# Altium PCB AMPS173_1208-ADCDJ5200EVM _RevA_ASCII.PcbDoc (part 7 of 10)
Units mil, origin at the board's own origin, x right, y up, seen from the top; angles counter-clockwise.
Board outline 10500 x 2750 mil, 14 copper layers (Top Copper, Layer 2 (GND1), Layer 3 (SIG1), Layer 4 (GND2, Layer 5 (PWR1), Layer 6 (GND3), Layer 7 (PWR/SIGNAL2), Layer 8 (PWR/SIGNAL3), Layer 9 (GND4), Layer 10 PWR2), Layer 11 (GND5), Layer 12 (SIG4), Layer 13 (GND6), Bottom Copper), stack 60.6 mil thick; 701 components, 826 nets, 3386 pads, 2128 vias.
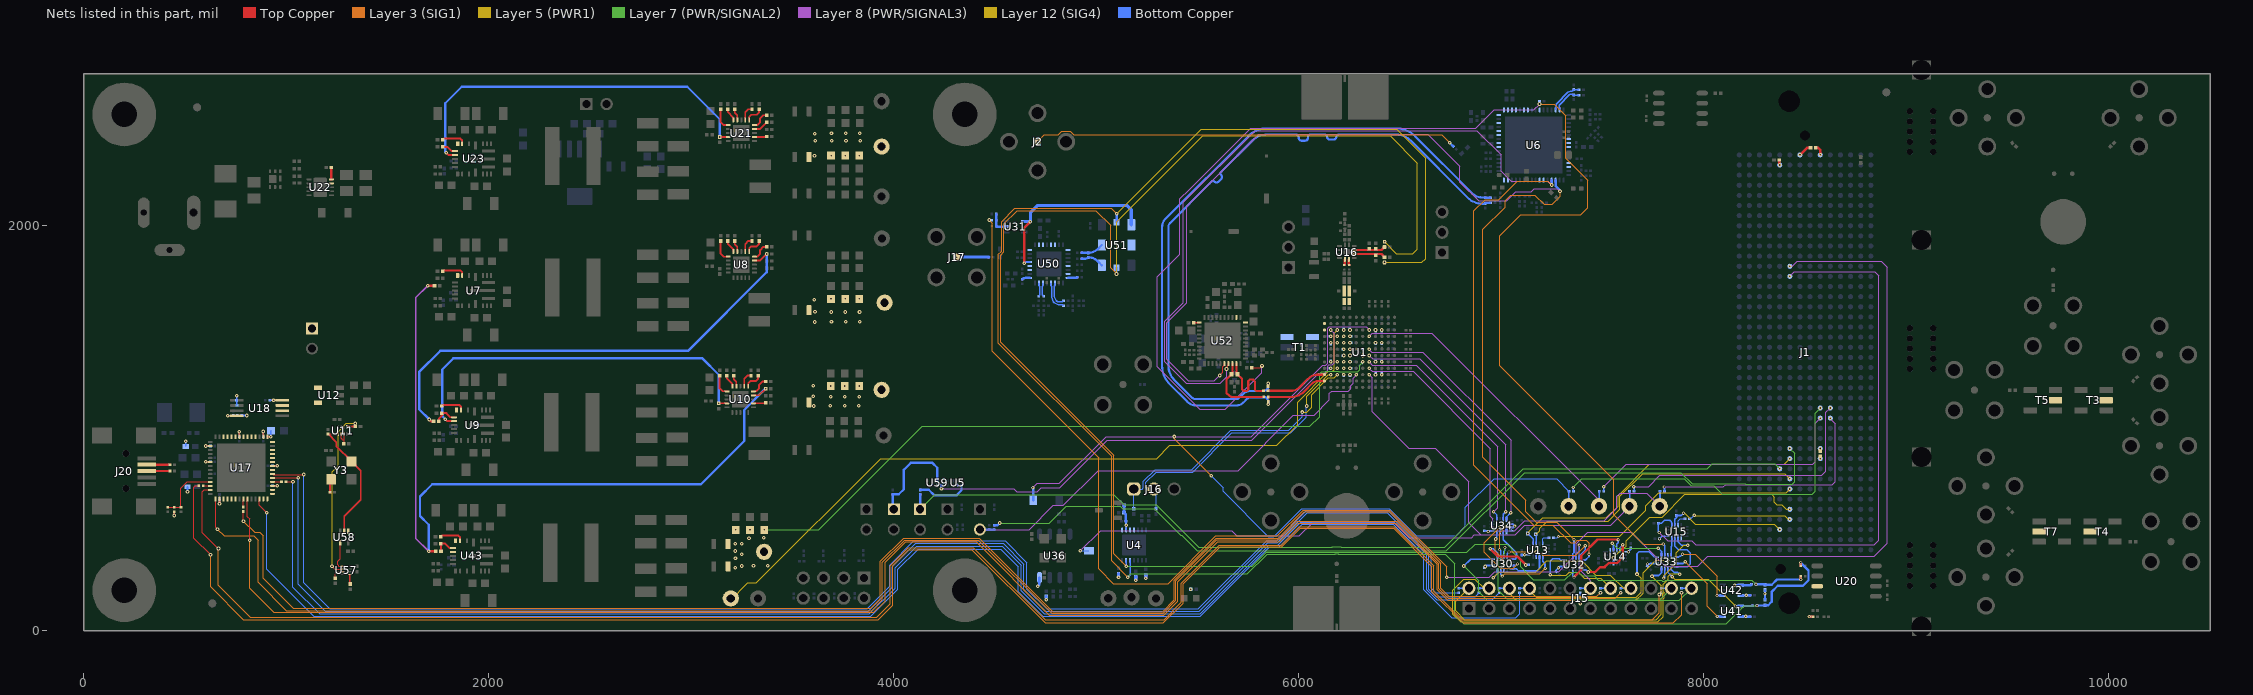
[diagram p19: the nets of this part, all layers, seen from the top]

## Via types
v1: diameter 18, hole 8, Top Copper to Bottom Copper, tented both sides, 1234 vias
v2: diameter 18, hole 8, Top Copper to Bottom Copper, tented top, 219 vias
v3: diameter 16, hole 8, Top Copper to Bottom Copper, tented both sides, 138 vias
v4: diameter 19.68, hole 7.87, Top Copper to Bottom Copper, 103 vias
v5: diameter 20, hole 10, Top Copper to Bottom Copper, tented top, 96 vias
v6: diameter 20, hole 10, Top Copper to Bottom Copper, tented both sides, 71 vias
v7: diameter 15.75/18/18/18/16/18/18/18/18/16/18/18/18/18 (per signal layer), hole 8, Top Copper to Bottom Copper, 50 vias
v8: diameter 20, hole 10, Top Copper to Bottom Copper, 40 vias
v9: diameter 15.75, hole 7.87, Top Copper to Bottom Copper, 28 vias
v10: diameter 21.81, hole 10, Top Copper to Bottom Copper, 26 vias
v11: diameter 15.75/16/16/16/16/16/16/16/16/16/16/16/16/18 (per signal layer), hole 8, Top Copper to Bottom Copper, 26 vias
v12: diameter 18, hole 8, Top Copper to Bottom Copper, tented bottom, 18 vias
v13: diameter 25.75, hole 15.75, Top Copper to Bottom Copper, 16 vias
v14: diameter 15.75/16/16/16/16/16/16/18/16/16/16/16/16/18 (per signal layer), hole 8, Top Copper to Bottom Copper, 15 vias
v15: diameter 30, hole 15, Top Copper to Bottom Copper, tented both sides, 12 vias
v16: diameter 15.75/16/16/16/18/16/16/16/16/16/16/16/16/18 (per signal layer), hole 8, Top Copper to Bottom Copper, 11 vias
v17: diameter 15.75/16/16/16/16/16/16/16/16/18/16/16/16/18 (per signal layer), hole 8, Top Copper to Bottom Copper, 7 vias
v18: diameter 15.75/16/16/16/16/16/16/18/16/18/16/16/16/18 (per signal layer), hole 8, Top Copper to Bottom Copper, 5 vias
v19: diameter 119.29, hole 77.95, Top Copper to Bottom Copper, 4 vias
v20: diameter 18, hole 8, Top Copper to Bottom Copper, 4 vias
v21: diameter 15.75/16/16/16/18/16/16/18/16/16/16/16/16/18 (per signal layer), hole 8, Top Copper to Bottom Copper, 2 vias
v22: diameter 15.75/16/16/16/16/16/18/16/16/16/16/16/16/18 (per signal layer), hole 8, Top Copper to Bottom Copper, 2 vias
v23: diameter 15.75/16/16/16/16/16/18/18/16/16/16/16/16/18 (per signal layer), hole 8, Top Copper to Bottom Copper, 1 vias

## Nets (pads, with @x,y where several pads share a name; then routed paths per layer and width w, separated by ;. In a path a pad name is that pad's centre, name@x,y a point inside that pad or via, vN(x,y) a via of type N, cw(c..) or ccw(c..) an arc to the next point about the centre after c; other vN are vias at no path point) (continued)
NetR99_1: R99.1 U7.16 | length 118
  Top Copper w9.8: R99.1@1772.99,1775 1777.99,1780 1860,1780 1868.9,1771.1 U7.16@1868.9,1754.8
NetR100_2: R100.2 U8.11 | length 106.1
  Top Copper w9: R100.2@3145,1925 3145,1862 3159.63,1847.37 U8.11@3182.04,1847.37
NetR101_2: R101.2 U8.10 | length 63.5
  Top Copper w9: R101.2@3180,1925 3180,1912 3207.63,1884.37 U8.10@3207.63,1872.96
NetR102_2: R102.2 U8.9 | length 57.1
  Top Copper w9: R102.2@3215,1925 3215,1908 3227.32,1895.69 U8.9@3227.32,1872.96
NetR110_2: R110.2 U8.7 | length 76.4
  Top Copper w9: U8.7@3266.69,1872.96 3266.69,1909.69 3282,1925 R110.2@3300,1925
NetR111_2: R111.2 U8.6 | length 87.7
  Top Copper w9: U8.6@3286.37,1872.96 3286.37,1888.37 3296,1898 3322.54,1898 3335,1910.46 R111.2@3335,1925
NetR112_2: R112.2 U8.5 | length 90.6
  Top Copper w9: U8.5@3311.96,1847.37 3325.37,1847.37 3340,1862 3340,1880 3355.75,1895.75 R112.2@3372.01,1895.75
NetR116_2: R116.2 U9.19 U10.14 | length 1903.9
  Top Copper w9: R116.2@3135,1122.99 v1(3135.32,1123.31) U10.14@3177.04,1123.31
  Top Copper w9.8: v1(1785,1045) 1795.32,1034.68 U9.19@1828.46,1034.68
  Bottom Copper w11.5: v1(1785,1045) 1770,1060 1770,1290 1825,1345 3055,1345 3135.32,1264.68 v1(3135.32,1123.31)
NetR117_1: R117.1 R280.1 U9.18 | length 115.5
  Top Copper w9.8: R280.1@1752.99,1035 1752.99,1047.99 1767.5,1062.5 1767.99,1062.5 R117.1@1767.99,1075 1790,1075 1810.63,1054.37 U9.18@1828.46,1054.37
NetR118_1: R118.1 U10.2 | length 61.1
  Top Copper w9: U10.2@3306.96,1123.31 3364.57,1123.31 R118.1@3367.01,1125.75
NetR119_1: R119.1 U9.16 | length 118
  Top Copper w9.8: R119.1@1767.99,1110 1772.99,1115 1855,1115 1863.9,1106.1 U9.16@1863.9,1089.8
NetR120_2: R120.2 U10.11 | length 106.1
  Top Copper w9: R120.2@3140,1260 3140,1197 3154.63,1182.37 U10.11@3177.04,1182.37
NetR122_2: R122.2 U10.10 | length 63.5
  Top Copper w9: R122.2@3175,1260 3175,1247 3202.63,1219.37 U10.10@3202.63,1207.96
NetR123_2: R123.2 U10.9 | length 57.1
  Top Copper w9: R123.2@3210,1260 3210,1243 3222.32,1230.68 U10.9@3222.32,1207.96
NetR124_2: R124.2 U10.7 | length 76.4
  Top Copper w9: U10.7@3261.69,1207.96 3261.69,1244.69 3277,1260 R124.2@3295,1260
NetR125_2: R125.2 U10.6 | length 87.7
  Top Copper w9: U10.6@3281.37,1207.96 3281.37,1223.37 3291,1233 3317.54,1233 3330,1245.46 R125.2@3330,1260
NetR126_2: R126.2 U10.5 | length 90.6
  Top Copper w9: U10.5@3306.96,1182.37 3320.37,1182.37 3335,1197 3335,1215 3350.75,1230.75 R126.2@3367.01,1230.75
NetR127_1: R127.1 U11.5 U57.2 | length 892.2
  Top Copper w6: v1(1226,318) 1239.11,304.89 U57.2@1278.28,304.89
  Top Copper w9: U11.5@1299.92,1006.58 1302.2,1008.87 R127.1@1340.13,1008.87 v1(1340.13,1023.75)
  Layer 12 (SIG4) w6: v1(1226,318) 1226,786 1256,816 1256,983 1296.75,1023.75 v1(1340.13,1023.75)
NetR128_1: R128.1 U11.2 U11.3 | length 86.5
  Top Copper w6: U11.2@1271.24,971.15 1271.24,949.76 1277,944 1285,944 ; R128.1@1283.01,923 1285,924.99 1285,944 ; U11.3@1285.02,971.15 1285.02,944.02
NetR129_1: R129.1 U57.3 | length 63.1
  Top Copper w4: R129.1@1241,259.99 1241,282 1250.11,291.11 U57.3@1278.28,291.11
NetR132_1: R132.1 U21.14 U23.19 | length 1879.6
  Top Copper w9: R132.1@3140,2437.99 v1(3140.32,2438.31) U21.14@3182.04,2438.31
  Top Copper w9.8: v1(1790,2360) 1800.32,2349.68 U23.19@1833.46,2349.68
  Bottom Copper w11.5: v1(1790,2360) 1785,2365 1785,2605 1866,2686 2980,2686 3140.32,2525.68 v1(3140.32,2438.31)
NetR134_1: R134.1 U23.18 | length 69
  Top Copper w9.8: R134.1@1772.99,2390 1795,2390 1815.63,2369.37 U23.18@1833.46,2369.37
NetR135_1: R135.1 U21.2 | length 61.1
  Top Copper w9: U21.2@3311.96,2438.31 3369.57,2438.31 R135.1@3372.01,2440.75
NetR136_1: R136.1 U23.16 | length 118
  Top Copper w9.8: R136.1@1772.99,2425 1777.99,2430 1860,2430 1868.9,2421.1 U23.16@1868.9,2404.8
NetR137_2: R137.2 U21.11 | length 106.1
  Top Copper w9: R137.2@3145,2575 3145,2512 3159.63,2497.37 U21.11@3182.04,2497.37
NetR139_2: R139.2 U21.10 | length 63.5
  Top Copper w9: R139.2@3180,2575 3180,2562 3207.63,2534.37 U21.10@3207.63,2522.96
NetR140_2: R140.2 U21.9 | length 57.1
  Top Copper w9: R140.2@3215,2575 3215,2558 3227.32,2545.68 U21.9@3227.32,2522.96
NetR141_2: R141.2 U21.7 | length 76.4
  Top Copper w9: U21.7@3266.69,2522.96 3266.69,2559.69 3282,2575 R141.2@3300,2575
NetR142_2: R142.2 U21.6 | length 87.7
  Top Copper w9: U21.6@3286.37,2522.96 3286.37,2538.37 3296,2548 3322.54,2548 3335,2560.46 R142.2@3335,2575
NetR143_2: R143.2 U21.5 | length 90.6
  Top Copper w9: U21.5@3311.96,2497.37 3325.37,2497.37 3340,2512 3340,2530 3355.75,2545.75 R143.2@3372.01,2545.75
NetR145_2: R145.2 U22.10 | length 58.5
  Top Copper w11.5: U22.10@1222.55,2229.5 R145.2@1222.55,2288
NetR153_1: R153.1 U17.12 | length 34.8
  Top Copper w5: R153.1@590.02,716 624.74,716 U17.12@624.82,715.92
NetR155_1: R155.1 U17.22 | length 39.6
  Top Copper w6: U17.22@788.2,650.96 788.5,650.66 R155.1@788.5,611.52
NetR160_2: R160.2 U17.6 | length 43.8
  Top Copper w5: v1(603.03,834.03) U17.6@624.82,834.03
  Bottom Copper w5: v1@603.06,834 R160.2@624.98,834
NetR162_2: R162.2 R165.2 R166.1 U17.11 | length 317.9
  Top Copper w5: R162.2@414,610.02 R165.2@447,610 R166.1@480,610.02 480,704 511.6,735.6 U17.11@624.82,735.6
NetR163_1: R163.1 U17.32 | length 44.1
  Top Copper w5: U17.32@931.91,735.6 975.87,735.6 R163.1@975.98,735.5
NetR169_1: R169.1 R170.1 U18.4 | length 93.9
  Top Copper w5: v1(710.59,1061.41) U18.4@756,1061.41
  Bottom Copper w5: v1(710.59,1061.41) 713.16,1063.98 R170.1@737,1063.98 R169.1@757.98,1064
NetR175_2: R175.2 U11.1 U58.2 Y3.3 | length 632.7
  Top Copper w5: R175.2@1208.76,973.12 U11.1@1257.46,973.12
  Top Copper w7: R175.2@1208.76,973.12 ccw(c1208.76,969.22) R175.2@1206,971.98 1247,930.98 1247,911.28 Y3.3@1322.13,836.16 1368,790.28 1368,648 1286,566 U58.2@1286,492.13
NetR178_1: R178.1 U13.4 | length 58.5
  Bottom Copper w6: U13.4@7204.37,429.84 7204.37,454.37 7210,460 R178.1@7235.98,460
NetR180_1: R180.1 U16.12 | length 26.5
  Top Copper w11.5: U16.12@6246.92,1833.67 6246.92,1809.99 R180.1@6248.92,1807.99
NetR181_2: R181.2 R182.1 R184.2
NetR182_2: R182.2 R183.1
NetR185_1: R185.1 U16.11 | length 26.6
  Top Copper w11.5: R185.1@6224.92,1807.99 6227.23,1810.31 U16.11@6227.23,1833.67
NetR186_2: R186.2 R187.1 R189.2
NetR187_2: R187.2 R188.1
NetR207_1: R207.1 U15.3 | length 61.1
  Bottom Copper w6: U15.3@7872.87,521.5 7872.87,542.87 7884,554 R207.1@7907.98,554
NetR226_1: R226.1 R238.2 U6.62 | length 169.7
  Bottom Copper w7: U6.62@7268.58,2572.05 7268.58,2583.34 cw(c7278.29,2583.34) 7269.26,2586.9 ccw(c7264.02,2592.13) 7271.05,2589.81 ccw(c7264.02,2592.13) 7271.43,2592.13 7271.43,2596 cw(c7285.43,2596) 7275.52,2605.89 ; 7275.53,2605.9 7326.29,2656.66 cw(c7344,2638.96) 7344,2664 ccw(c7344,2676.64) 7352.94,2667.7 R238.2@7358.19,2672.95 ccw(c7360.55,2675.31) 7360.55,2671.98 R226.1@7383.17,2671.98
NetR227_1: R227.1 R256.2 U6.63 | length 145.7
  Bottom Copper w7: U6.63@7288.27,2572.05 7288.27,2583.34 cw(c7295.13,2590.21) 7285.43,2590.21 7285.43,2596 7336.19,2646.77 cw(c7344,2638.96) 7344,2650 7346.12,2650 cw(c7346.12,2632.93) R256.2@7358.19,2645 R227.1@7383.17,2644.98
NetR230_1: R230.1 R888.1 U43.18 | length 106.9
  Top Copper w9.8: R888.1@1763.78,392.43 1762.99,393.22 R230.1@1762.99,430 1785,430 1805.63,409.37 U43.18@1823.46,409.37
NetR231_1: R231.1 U43.16 | length 118
  Top Copper w9.8: R231.1@1762.99,465 1767.99,470 1850,470 1858.9,461.1 U43.16@1858.9,444.8
NetR233_1: R233.1 U57.5 | length 47.3
  Top Copper w7: R233.1@1313.72,233.28 U57.5@1313.72,277.33
  Top Copper w11.5: R233.1@1313.72,233.28 R233.1@1316,230.99
NetR239_1: R239.1 U50.9 | length 38.6
  Bottom Copper w11.5: R239.1@4635,1736.02 cw(c4651.06,1719.96) 4651.06,1742.68 U50.9@4671.81,1742.68
NetR240_1: R240.1 U50.3 | length 129.1
  Bottom Copper w7: U50.3@4795.83,1717.09 4795.83,1705.8 ccw(c4802.69,1698.93) 4792.98,1698.93 4792.98,1653.92 ccw(c4826.91,1653.92) 4802.92,1629.93 ccw(c4816.51,1643.52) 4816.51,1624.3 4829.14,1624.3 ccw(c4829.14,1631.81) 4834.45,1626.5 R240.1@4837.95,1630
NetR241_1: R241.1 U50.32 | length 46.4
  Bottom Copper w11.5: U50.32@4860.79,1742.68 4903.46,1742.68 R241.1@4906.06,1745.28
NetR242_1: R242.1 U50.4 | length 151
  Bottom Copper w7: U50.4@4776.14,1717.09 4776.14,1705.8 cw(c4769.28,1698.93) 4778.98,1698.93 4778.98,1653.92 ccw(c4826.91,1653.92) 4793.02,1620.03 ccw(c4816.51,1643.52) 4816.51,1610.3 4830.11,1610.3 cw(c4830.11,1604.15) 4834.45,1608.5 R242.1@4837.95,1605
NetR246_1: R246.1 U50.6 | length 67.9
  Bottom Copper w7: U50.6@4736.77,1717.09 4736.77,1705.8 ccw(c4743.63,1698.93) 4733.93,1698.93 4733.93,1661.75 ccw(c4742.71,1661.75) 4736.5,1655.55 R246.1@4740,1652.05
NetR247_1: R247.1 U50.7 | length 67.6
  Bottom Copper w7: R247.1@4715,1652.05 4718.5,1655.55 ccw(c4715.05,1659) 4719.93,1659 4719.93,1698.93 ccw(c4710.22,1698.93) 4717.09,1705.8 U50.7@4717.09,1717.09
NetR254_1: R254.1 U5.4 | length 249.8
  Bottom Copper w11.5: R254.1@4130,696.02 4172.98,696.02 4199,670 4311,670 4334.69,693.68 U5.4@4334.69,718.19
NetR262_1: R262.1 U52.1 | length 27.7
  Top Copper w8: R262.1@5481.2,1521.79 5481.36,1521.96 U52.1@5508.86,1521.96
NetR277_1: R277.1 R278.1 R279.2 U31.2 | length 111
  Bottom Copper w11.5: R279.2@4506.02,2058.19 R278.1@4506.02,2028.19 R277.1@4506.02,1998.19 4509.21,1995 U31.2@4555.71,1995
NetR305_1: R305.1 U30.1 | length 291.4
  Top Copper w11.5: v1(6945,405) 6983.58,366.42 7079.96,366.42 v1(7121.38,325)
  Bottom Copper w7: v1(6945,405) 6960,405 6981.38,383.62 U30.1@6981.38,359.53
  Bottom Copper w11.5: v1(7121.38,325) R305.1@7133.98,325
NetR801_2: R801.2 Y3.1 | length 65.7
  Top Copper w11.5: R801.2@1215.87,684.44 1215.87,741.32 Y3.1@1222.13,747.57
NetR804_1: R804.1 U42.4 | length 84.8
  Bottom Copper w11.5: v3(8153,225) U42.4@8182.29,225 8231.54,225 R804.1@8235.95,229.41
NetR852_1: R852.1 U33.10 U41.4 | length 508
  Layer 12 (SIG4) w3.3: v3(7844,267) 7856,255 8023,255 v3(8155.68,122.32)
  Bottom Copper w8: U33.10@7822.87,308.5 7822.87,288.13 v3(7844,267)
  Bottom Copper w11.5: v3(8155.68,122.32) U41.4@8182.29,122.32 8238.87,122.32 R852.1@8240.95,124.41
NetT1_1: T1.1
NetT1_6: T1.6
NetT3_2: T3.2
NetT4_2: T4.2
NetT5_2: T5.2
NetT7_2: T7.2
NetU1_B1: U1.B1
NetU1_C1: U1.C1
NetU4_1: U4.1
NetU4_3: U4.3
NetU4_4: U4.4
NetU5_5: U5.5
NetU6_7: U6.7
NetU6_8: U6.8
NetU6_9: U6.9
NetU6_13: U6.13
NetU6_14: U6.14
NetU6_22: U6.22
NetU6_23: U6.23
NetU6_31: U6.31
NetU6_32: U6.32
NetU6_40: U6.40
NetU6_41: U6.41
NetU6_43: U6.43
NetU6_44: U6.44
NetU6_46: U6.46
NetU6_48: U6.48
NetU6_49: U6.49
NetU6_50: U6.50
NetU6_51: U6.51
NetU6_52: U6.52
NetU6_54: U6.54
NetU6_55: U6.55
NetU6_58: U6.58
NetU7_17: U7.17
NetU9_17: U9.17
NetU12_4: U12.4
NetU12_5: U12.5
NetU13_9: U13.9 U30.11 | length 323.6
  Layer 3 (SIG1) w3.3: v3(7005,270) 7016,281 7190,281 v3(7217,308)
  Bottom Copper w8: U30.11@6997.13,298.5 6997.13,277.87 v3(7005,270) ; U13.9@7204.37,366.85 7204.37,342.63 7216,331 7216,309 v3(7217,308)
NetU13_10: U13.10 U30.8 | length 205
  Bottom Copper w8: U30.8@7052.24,306.38 7073.62,306.38 7085,295 7175,295 7188.68,308.68 7188.68,366.79 U13.10@7188.62,366.85
NetU13_11: U13.11 U30.4 U32.4 | length 536
  Layer 3 (SIG1) w3.3: v3(7038,389) 7038.65,389.65 7172.4,389.65 v3(7172.87,390.13) 7185.87,390.13 7204,372 7367,372 v3(7415,420)
  Bottom Copper w8: U30.4@7028.62,361.5 7028.62,379.62 v3(7038,389) ; U13.11@7172.87,366.85 v3(7172.87,390.13) ; U32.4@7383.62,356.5 7383.62,367.62 7415,399 v3(7415,420)
NetU14_9: U14.9
NetU14_10: U14.10 U33.1 | length 319.8
  Layer 7 (PWR/SIGNAL2) w3.3: v3(7548,432) 7572,408 v3(7775,408) v3@7776.01,408
  Bottom Copper w8: v3(7548,432) 7554.25,425.75 U14.10@7554.25,397.99 ; v3(7775,408) 7791.38,391.62 U33.1@7791.38,369.53
NetU14_11: U14.11 U32.11 | length 421.3
  Top Copper w11.5: v3(7359,265) 7395,301 7395,370 7475.75,450.75 7575.25,450.75 v3(7577,449)
  Bottom Copper w8: U32.11@7352.13,293.5 7352.13,271.87 v3(7359,265) ; U14.11@7570,397.99 7570,428 7577,435 v3(7577,449)
NetU14_12: U14.12 U32.8 | length 322
  Top Copper w11.5: v1(7430,290) 7464.14,290 7488.39,314.25 7510.25,314.25 7531,335 7571,335 7600,364 v1(7600,425)
  Bottom Copper w8: U32.8@7407.24,301.38 7418.62,301.38 v1(7430,290) ; U14.12@7585.75,397.99 7585.75,410.75 v1(7600,425)
NetU15_9: U15.9
NetU15_10: U15.10 U33.11 | length 349.4
  Layer 12 (SIG4) w3.3: v3@7803.01,260 7803.01,272 7864.01,333 7864.01,386 7900.01,422 v3(7921,422) v3@7922.01,422
  Bottom Copper w8: v3(7802,260) 7807.13,265.13 U33.11@7807.13,308.5 ; U15.10@7872.87,458.5 7872.87,439.13 7890,422 v3(7921,422)
NetU15_11: U15.11 U33.8 | length 261.6
  Bottom Copper w8: U15.11@7857.13,458.5 7857.13,418.13 7875.25,400 7917,400 7934,383 7934,331 7919.38,316.38 U33.8@7862.24,316.38
NetU15_12: U15.12 U33.4 | length 88.1
  Bottom Copper w8: U33.4@7838.62,371.5 7838.62,416.24 7841.38,419 U15.12@7841.38,458.5
NetU17_17: U17.17
NetU17_18: U17.18
NetU17_19: U17.19
NetU17_20: U17.20
NetU17_27: U17.27
NetU17_28: U17.28
NetU17_29: U17.29
NetU17_30: U17.30
NetU17_35: U17.35
NetU17_37: U17.37
NetU17_38: U17.38
NetU17_39: U17.39
NetU17_40: U17.40
NetU17_42: U17.42
NetU17_46: U17.46
NetU17_47: U17.47
NetU17_48: U17.48
NetU17_49: U17.49
NetU17_51: U17.51
NetU17_52: U17.52
NetU17_53: U17.53
NetU17_54: U17.54
NetU18_6: U18.6
NetU18_7: U18.7
NetU20_7: U20.7
NetU22_9: U22.9
NetU23_17: U23.17
NetU30_2: U30.2 U34.1 | length 196.9
  Layer 3 (SIG1) w3.3: v3@6992.01,401 6992.01,484 v3@7023.01,515
  Bottom Copper w8: v3(6991,401) 6997.13,394.87 U30.2@6997.13,361.5 ; v3(7022,515) 7025.62,511.38 U34.1@7025.62,488.47
NetU30_5: U30.5 U34.2 | length 178.9
  Bottom Copper w8: U34.2@7009.87,486.5 7009.94,486.44 7009.94,450.06 7075,385 7075,360 7068.62,353.62 U30.5@7052.24,353.62
NetU30_7: U30.7 U34.3 | length 425.3
  Layer 3 (SIG1) w3.3: v3@6995.13,513.87 6916,434.74 6916,387.66 6994.69,308.97 7059.98,308.97 v3@7081.01,330
  Bottom Copper w8: v3@6993,515 v3(6994.13,513.87) U34.3@6994.13,486.5 ; U30.7@7052.24,322.13 7072.13,322.13 v3(7080,330)
NetU30_10: U30.10 U34.4 | length 208.4
  Layer 3 (SIG1) w3.3: v1(6972,453) 6971.01,452.01 6971.01,392.19 7010,353.2 v3(7010,325)
  Bottom Copper w8: v1(6972,453) 6978.38,459.38 U34.4@6978.38,486.5 ; v3(7010,325) 7012.87,322.13 U30.10@7012.87,298.5
NetU31_4: U31.4 U50.13 U51.1 | length 917.9
  Top Copper w11.5: v1(4645,1815) 4645,1991.18 v1(4674.41,2020.59)
  Bottom Copper w11.5: v1(4645,1815) 4651.42,1821.42 U50.13@4671.81,1821.42
  Bottom Copper w15.5: U31.4@4644.29,2020.59 v1(4674.41,2020.59) 4674.41,2064.94 4710.25,2100.78 5150.92,2100.78 5172.83,2078.87 U51.1@5172.83,2005
NetU33_5: U33.5 U42.1 | length 378.5
  Layer 3 (SIG1) w3.3: v3@7896.01,378 7958.01,378 8066.19,269.82 v3@8066.19,173.82
  Bottom Copper w8: U33.5@7862.24,363.62 7875.58,363.62 7879.96,368 7885,368 v3(7895,378)
  Bottom Copper w11.5: v3@8065,174 v3(8065.18,173.82) U42.1@8093.71,173.82
NetU33_7: U33.7 U41.1 | length 412.6
  Layer 3 (SIG1) w3.3: v3@7909.01,341 8017.4,232.61 8017.4,120.61 v3@8067.01,71
  Bottom Copper w8: U33.7@7862.24,332.13 7899.13,332.13 v3(7908,341)
  Bottom Copper w11.5: v3(8066,71) 8066.14,71.14 U41.1@8093.71,71.14
NetU43_17: U43.17
NetU43_19: U43.19
NetU50_11: U50.11
NetU50_12: U50.12
NetU50_16: U50.16
NetU50_18: U50.18
NetU50_19: U50.19
NetU50_21: U50.21
NetU50_22: U50.22
NetU50_25: U50.25
NetU50_29: U50.29
NetU50_31: U50.31
NetU51_2: U51.2
NetU52_30: U52.30
NetU52_32: U52.32
NetU57_1: U57.1 U58.4 | length 144.3
  Top Copper w6: U58.4@1266.32,433.87 1266.32,356.32 1253,343 1253,325 1259.33,318.67 U57.1@1280.25,318.67
NetU58_1: U58.1
NetU59_5: U59.5
ORA0_ADC: D4.2 R33.2 TP8.1 U1.C8 | length 4717
  Layer 3 (SIG1) w5: v1(5385,959) 5385,948 v1(5567,766)
  Layer 8 (PWR/SIGNAL3) w3.3: v3(4687,706) 4709,728 4818,728 5049,959 v1(5385,959) 5766,959 6118.91,1311.91 6133.06,1311.91 6142.62,1321.47 6142.62,1493.62 6150,1501 6332.49,1501 6348.25,1485.24 v14(6347.24,1485.24)
  Bottom Copper w5: v1(5567,766) 5626,707 5626,688.95 5849.95,465 5876,465 6014,603 6447,603 6581,469 6777,469 6823,515 6823,608.95 6965,750.95 7273.02,750.95 R33.2@7333.98,690
  Bottom Copper w8: TP8.1@7332.5,615 7333.98,616.48 R33.2@7333.98,690
  Bottom Copper w11.5: v3(4687,706) 4688.52,704.48 D4.2@4688.52,644.57
ORA0_FMC: J1.D26 R33.1 | length 1692.8
  Layer 7 (PWR/SIGNAL2) w4: v3(7355,708) 7397.95,750.95 7904.27,750.95 7939.27,715.95 8048,715.95 8090,673.95 8536,673.95 8550,687.95 8550,1075 v1(8575,1100)
  Layer 7 (PWR/SIGNAL2) w8: v3(7355,708) v3@7356.02,706.98
  Bottom Copper w8: v3(7355,708) 7356.02,706.98 R33.1@7356.02,690
ORA1_ADC: R36.2 TP12.1 U1.D8 | length 1588.4
  Layer 8 (PWR/SIGNAL3) w3.3: v14@6348.25,1453.74 6348.25,1454.24 6363.59,1469.59 6657.41,1469.59 7483,644 7483,615.5 TP12.1@7483.51,615
  Bottom Copper w8: TP12.1@7482.5,615 7483.98,616.48 R36.2@7483.98,690
  other v14: 6347.24,1453.74
ORA1_FMC: J1.D27 R36.1 | length 1342.9
  Layer 8 (PWR/SIGNAL3) w4: v3(7506,711) 7616.95,821.95 8539,821.95 8551,833.95 8551,1026 v1(8575,1050)
  Bottom Copper w8: R36.1@7506.02,690 v3(7506,711)
ORB0_ADC: D5.2 R71.2 TP13.1 U1.K8 | length 4098.6
  Layer 8 (PWR/SIGNAL3) w3.3: v1(4921.47,394.47) 5021,494 5669,494 5694,469 6003,469 6068,534 6472,534 6546,460 6853,460 6867.35,474.35 6898.65,474.35 ; v14@6348.25,1264.76 6363,1250.02 6363,1081.69 6543,901.69 6673.85,901.69 6839.31,736.23 6839.31,533.69 6898.65,474.35 ; TP13.1@7633.51,615 7540.64,522.13 7116.23,522.13 7068.46,474.35 6898.65,474.35
  Bottom Copper w4: v1(4921.47,394.47) D5.2@4964,394.47
  Bottom Copper w8: TP13.1@7632.5,615 7633.98,616.48 R71.2@7633.98,690
  other v14: 6347.24,1264.76
ORB0_FMC: J1.C26 R71.1 | length 1324.5
  Layer 8 (PWR/SIGNAL3) w4: v3(7654,711) 7727.05,711 7783.52,767.48 8583.52,767.48 8603,786.95 8603,1078 v1(8625,1100)
  Bottom Copper w8: v3(7654,711) 7656.02,708.98 R71.1@7656.02,690
ORB1_ADC: R82.2 TP14.1 U1.J8 | length 2201
  Layer 8 (PWR/SIGNAL3) w3.3: v14@6348.25,1294.76 6362.4,1280.61 6564.39,1280.61 6946.35,898.65 6946.35,564.66 6957,554.01 6957,513 6977,493 7066.28,493 7116.01,542.73 7507.73,542.73 7571.01,606 7571.01,664 7587.01,680 7718.51,680 TP14.1@7783.51,615
  Bottom Copper w8: TP14.1@7782.5,615 7783.98,616.48 R82.2@7783.98,690
  other v14: 6347.24,1296.26
ORB1_FMC: J1.C27 R82.1 | length 1200.6
  Layer 8 (PWR/SIGNAL3) w4: v3(7804,710) 8097,710 8108,721 8634.05,721 8649,735.95 8649,1022.95 8625,1046.95 v1(8625,1050)
  Bottom Copper w8: v3(7804,710) 7806.02,707.98 R82.1@7806.02,690
PD_ADC: J12.2 R27.1 R28.2 U1.K6 | length 2289.9
  Layer 8 (PWR/SIGNAL3) w3.3: J12.2@4426.01,500 4669.01,500 4788.5,619.5 4838,619.5 5009.5,791 5700.16,791 5973.51,1064.35 6075.51,1064.35 6150.96,1139.81 6150.96,1172.66 6161.59,1183.28 6243.43,1183.28 6256,1195.85 6256,1210.44 6268.6,1223.04 6268.6,1248.11 v21@6285.26,1264.76
  Bottom Copper w11.5: J12.2@4425,500 4426.02,498.98 R27.1@4496.02,498.98
  other v21: 6284.25,1264.76
PD_FMC: J1.G30 R27.2 | length 4453.5
  Layer 7 (PWR/SIGNAL2) w4: v20(4523,532) 4767.05,532 4850.97,615.92 5117.61,615.92 5131.58,601.95 5286,601.95 5417.27,470.68 5422.54,470.68 5498.05,395.18 6172.12,395.18 6173.08,396.14 6200.92,396.14 6201.88,395.18 6729.22,395.18 7115,780.95 7887,780.95 7943,724.95 8205.82,724.95 8206.77,724 8438.05,724 8449,734.95 8449,876 v1(8425,900)
  Layer 5 (PWR1) w3.3: v1@8425,893.95 v1(8425,900)
  Bottom Copper w11.5: R27.2@4496.02,521.02 4512.02,521.02 v20(4523,532)
PG-1p1V: R92.2 R280.2 U8.4 | length 2363.7
  Top Copper w9: U8.4@3311.96,1827.68 3338.94,1827.68 v1(3372.01,1860.75)
  Top Copper w11.5: v1(1706.53,1043.47) 1715,1035 R280.2@1727.01,1035
  Bottom Copper w11.5: v1(1706.53,1043.47) 1656,1094 1656,1278 1760,1382 2984,1382 3372.01,1770.01 v1(3372.01,1860.75)
PG-1p9V: R113.2 R888.2 R950.2 U10.4 | length 3809.1
  Top Copper w9: U10.4@3306.96,1162.68 3333.94,1162.68 v1(3367.01,1195.75)
  Top Copper w11.5: v1(1697.85,1703.43) R950.2@1732.19,1703.43 ; v1(1703.46,392.43) R888.2@1737.8,392.43
  Layer 8 (PWR/SIGNAL3) w8: v1(1697.85,1703.43) 1640,1645.58 1640,455.89 v1(1703.46,392.43)
  Bottom Copper w11.5: v1(1703.46,392.43) 1703.46,523.26 1660,566.72 1660,662.8 1720.97,723.77 3047.55,723.77 3261.4,937.62 3261.4,1090.14 v1(3367.01,1195.75)
PG-3p3V: R130.2 U21.4 | length 73.7
  Top Copper w9: U21.4@3311.96,2477.68 3338.94,2477.68 R130.2@3372.01,2510.75
PG-C2M: J1.D1 R103.1 | length 50.9
  Top Copper w11.5: R103.1@8552.99,2385 8564.63,2385 8575,2374.63 v2(8575,2350)
PG-M2C: J1.F1 R103.2 | length 66.5
  Top Copper w11.5: v2(8475,2350) 8509.59,2384.59 8526.6,2384.59 R103.2@8527.01,2385
PRSNT-M2C-L: J1.H2 R104.1 | length 20.2
  Top Copper w11.5: v2@8372.99,2304.85 R104.1@8372.99,2325
  other v2: 8375,2300
REF_SEL_FMC: J1.G12 R278.2 | length 8294.2
  Layer 3 (SIG1) w3.3: v1(4471.38,2028.19) 4486.57,2013 4486.57,1379.43 5011.38,854.62 5011.38,305.62 5084,233 5356,233 5591,468 5894,468 6022,596 6450.26,596 6730,316.26 v1(6730,265)
  Layer 8 (PWR/SIGNAL3) w4: v1(6730,265) 6940.86,265 6967.86,292 7284.21,292 7370,377.79 7370,429.21 7427.74,486.95 7642,486.95 7810,318.95 7971,318.95 8020,367.95 8843,367.95 8906,430.95 8906,1794.95 8876,1824.95 8462,1824.95 8437.05,1800 v1(8425,1800)
REFCLK_OSC_N: C322.2 R251.1 U51.5 | length 112.6
  Bottom Copper w11.5: C322.2@4928.11,1867.09 ccw(c4930.68,1869.65) 4930.68,1866.02 R251.1@4960,1866.02 ccw(c4960,1934.08) 5008.12,1885.96 U51.5@5027.17,1905
REFCLK_OSC_P: C321.2 R251.2 U51.4 | length 114.1
  Bottom Copper w11.5: C321.2@4928.11,1837.09 4943.37,1837.09 ccw(c4943.37,1860.61) R251.2@4960,1843.98 cw(c4960,1775.92) 5008.12,1824.04 U51.4@5027.17,1805
REFCLK_SMA_P: J17.1 R245.1 | length 159
  Bottom Copper w15.5: v12(4310,1845) R245.1@4468.98,1845
SCL2_FMC: J1.G13 R80.2 U15.1 | length 3021.9
  Layer 8 (PWR/SIGNAL3) w4: v3(7780,485) 7821.05,443.95 7940,443.95 7960,423.95 8842,423.95 8865,446.95 8865,1752.95 8845,1772.95 8447.95,1772.95 v1(8425,1750)
  Bottom Copper w8: v3(7780,485) 7776.02,488.98 R80.2@7776.02,530 7790,530 7805,545 7830.18,545 cw(c7830.18,535.77) 7836.7,542.3 cw(c7825.42,531.01) 7841.38,531.01 U15.1@7841.38,519.53
SCL_AMP: R3.1 R7.2 R194.2 R195.1 U16.3 | length 164.2
  Top Copper w5: R7.2@6348,1880 R7.2@6348,1887.01 R7.2@6348,1888
  Top Copper w11.5: U16.3@6273.49,1879.93 6408.49,1879.93 R194.2@6423.49,1894.93
SCL_FMC: R195.2 R804.2 R805.1 R807.1 U4.13 U51.8 | length 8997.7
  Top Copper w11.5: v3(8478.98,253.02) R807.1@8478.98,270
  Layer 7 (PWR/SIGNAL2) w3.3: v1@5148.89,317.88 5771.11,317.88 5839.76,386.53 6175.7,386.53 6176.67,387.49 6197.33,387.49 6198.3,386.53 6829.78,386.53 6870.95,427.7 7029.3,427.7 7054.7,402.3 7054.7,390.37 7095.06,350 7095.06,314.93 7158,252 7314,252 7352,290 7380,290 7399,271 7458,271 7479,250 7791.28,250 7795.93,245.35 7808.07,245.35 7812.72,250 8237.41,250 v3(8258,229.41)
  Layer 3 (SIG1) w3.3: 4544,1870.48 4544,1871 ; v1@5100.86,1762.15 5070.2,1792.81 5070.2,2002.9 4998.1,2075 4609,2075 4544,2010 4544,1871 ; v1@5148.89,317.88 5086,380.77 5086,866 4528,1424 4528,1855 4544,1871
  Layer 5 (PWR1) w6: v1(5100,1762) 5100,2019 5525,2444 6451,2444 6586,2309 6586,1885 6564,1863 6482.38,1863 v1(6424.15,1921.23)
  Bottom Copper w9: v1(5147.88,317.88) U4.13@5147.88,348.67
  Bottom Copper w11.5: v1(5100,1762) U51.8@5100,1792.2 ; v3(8258,229.41) 8299.97,229.41 R805.1@8301.98,227.4 8335.4,227.4 8361.02,253.02 v3(8478.98,253.02)
SCL_HDR: J15.6 R149.2 U33.3 | length 1036.5
  Layer 12 (SIG4) w3.3: J15.6@7040,210 7040,185 7075,150 7665,150 7700.87,185.87 7700.87,285.87 7762,347 v3(7822,347)
  Bottom Copper w8: R149.2@6990,210 J15.6@7040,210 ; v3(7822,347) 7822.87,347.87 U33.3@7822.87,371.5
SCL_USB: R149.1 R163.2 | length 7435.3
  Top Copper w5: R163.2@998.02,735.5 v1(1033,735.5)
  Bottom Copper w5: v1(1033,735.5) 1033,215 1164,84 3880,84 4007,211 4007,310 4114,417 4535,417 4629,323 4629,197 4742,84 5513,84 5851,422 5896.14,422 6010.57,536.43 6470.29,536.43 6631,375.72 6631,203.31 6680.31,154 6956.05,154 R149.1@6990,187.95
SCLK_ADC: U1.F8 U34.12 | length 1287.6
  Layer 8 (PWR/SIGNAL3) w3.3: v14@6348.25,1390.75 6348.25,1387.76 6361.01,1375 6613,1375 7048.01,939.99 v3@7048.01,583
  Bottom Copper w8: U34.12@7025.62,549.5 7025.62,561.62 v3(7047,583)
  other v14: 6347.24,1390.75
SCLK_ADC_HDR: J15.24 R54.2 U30.16 | length 1459.2
  Layer 7 (PWR/SIGNAL2) w3.3: v1(6815,320) 6888,247 6888,192 6930,150 7880,150 J15.24@7940,210
  Bottom Copper w8: v1(6815,320) 6848.62,353.62 U30.16@6957.76,353.62 ; R54.2@7890,210 J15.24@7940,210
SCLK_ADC_USB: R54.1 R153.2 | length 8931
  Top Copper w4: R153.2@567.98,716 551,716 544,709 544,458 v1(626,376)
  Layer 3 (SIG1) w3.3: v1(626,376) 626,217 788,55 3923,55 3995,127 3995,321 4074,400 4386,400 4747.29,38.71 5330.39,38.71 5428.3,136.62 5428.3,231.56 5611.84,415.1 5916.04,415.1 6006.69,505.75 6469.09,505.75 6657.8,317.04 6657.8,192.2 6811.29,38.71 6852,38.71 7848.71,38.71 7890,80 v1(7890,188)
SCLK_FMC: J1.G31 R73.2 U13.1 | length 1548.4
  Layer 7 (PWR/SIGNAL2) w3.3: v3@7131.98,480.39 v3@7137.61,480.39
  Layer 12 (SIG4) w3.3: v3(7130.98,480.39) 7130.98,484.1 7203.82,556.95 7518,556.95 7576.85,615.8 7576.85,667.3 7731.51,821.95 8396.95,821.95 v1(8425,850)
  Bottom Copper w8: v3(7130.98,480.39) 7157.13,454.24 U13.1@7157.13,427.87
SCLK_LMKX: U6.19 U32.2 U52.16 | length 5853.2
  Top Copper w5: v1(5610.21,1260.79) 5625.21,1275.79 5625.21,1303.79 5632.87,1311.46 U52.16@5632.87,1319.2
  Layer 3 (SIG1) w3.3: v1(7290,2170) 7290,2144.8 7250.5,2105.3 7211.3,2105.3 7165.03,2151.57 7046.57,2151.57 7018.5,2123.5 7018.5,2091.2 6909,1981.7 6909,856 7121.1,643.9 7121.1,588.9 7173,537 7273.01,537 v3@7360.01,450
  Layer 8 (PWR/SIGNAL3) w3.3: v1(5610.21,1260.79) 5583.41,1234 5454,1234 5348,1340 5348,1522 5447,1621 5447,2096.95 5802.05,2452 6637,2452 6796,2293 6796,2215 6888,2123 7026,2123 7070.74,2167.74 7149,2167.74 7163.76,2182.5 7277.5,2182.5 v1(7290,2170)
  Bottom Copper w8: U32.2@7352.13,356.5 7352.13,379.63 7359,386.5 v3(7359,450)
  Bottom Copper w11.5: U6.19@7268.58,2225 7268.58,2210.76 7269.65,2209.7 7269.65,2195.6 7290,2175.25 v1(7290,2170)
SCLK_LMKX_HDR: J15.16 R79.2 U32.16 | length 535.1
  Layer 12 (SIG4) w3.3: v1(7241,276) 7243.07,273.93 7320.13,273.93 7335.8,289.6 7380.4,289.6 7410,260 7490,260 J15.16@7540,210
  Bottom Copper w8: v1(7241,276) 7242,277 7242,343 7254,355 7285.62,355 7292,348.62 U32.16@7312.76,348.62 ; R79.2@7490,210 J15.16@7540,210
SCLK_LMKX_USB: R79.1 R155.2 | length 7966.6
  Top Copper w4: v1(788.5,541.5) R155.2@788.5,589.48
  Layer 3 (SIG1) w3.3: v1(788.5,541.5) 844,486 870,486 887,469 887,259 1035,111 3886,111 3934,159 3934,343 4049,458 4421,458 4784,95 5327,95 5385,153 5385,250.26 5592.37,457.63 5897.63,457.63 6027,587 6447.52,587 6700,334.52 6700,210 6740,170 7472.05,170 v1(7490,187.95)
SDA2_I_FMC: J1.G37 R207.2 | length 510.7
  Layer 12 (SIG4) w4: v3(7953,571) 7955.9,568.1 8399.85,568.1 v1@8417.95,550
  Layer 12 (SIG4) w6: v1@8417.95,550 v1(8425,550)
  Bottom Copper w6: R207.2@7930.02,554 7936,554 v3(7953,571)
SDA2_O_FMC: J1.H38 R81.2 U15.2 | length 598.4
  Layer 12 (SIG4) w4: v3(7900,580) 7904.81,580 7958.86,525.95 8349.05,525.95 v1(8375,500)
  Bottom Copper w8: U15.2@7857.13,521.5 7857.13,550.08 7865,557.95 R81.2@7865,568.98 7888.98,568.98 v3(7900,580)
SDA_AMP: R4.1 R196.2 R197.1 U16.2 | length 156.3
  Top Copper w11.5: U16.2@6273.49,1860.25 6408.18,1860.25 R196.2@6423.49,1844.93
SDA_FMC: R197.2 R808.1 R851.1 R852.2 U4.12 U51.7 | length 9167.2
  Top Copper w11.5: v3(8478,337) 8478.98,336.02 R808.1@8478.98,320
  Layer 7 (PWR/SIGNAL2) w3.3: v1(5155,265) 5171,281 5745.97,281 5843.2,378.23 6179.14,378.23 6180.1,379.19 6193.9,379.19 6194.86,378.23 6722.77,378.23 6770,331 6770,79 6814,35 8111,35 8200.41,124.41 v3(8263,124.41)
  Layer 3 (SIG1) w3.3: v1(5101,2059) 5074,2086 4597,2086 4532,2021 4532,1875 4517,1860 4517,1420 5076,861 5076,345 v1@5156.01,265
  Layer 5 (PWR1) w6: v1(5101,2059) 5518,2476 6484,2476 6627,2333 6627,1838 6607.95,1818.95 v1(6423.49,1818.95)
  Bottom Copper w9: v1(5155,265) 5167.57,277.57 U4.12@5167.57,348.67
  Bottom Copper w11.5: U51.7@5100,2017.8 5101,2018.8 v1(5101,2059) ; v3(8263,124.41) 8299.97,124.41 R851.1@8301.98,126.42 8318.42,126.42 8335,143 8335,192 8365,222 8490,222 8517,249 8517,298 v3(8478,337)
SDA_HDR: J15.2 R151.2 U33.12 | length 1521.9
  Layer 12 (SIG4) w3.3: J15.2@6840,210 6775,145 6775,97.8 6817.8,55 7764.2,55 7791,81.8 7791,161 7796.65,166.65 7796.65,185.44 7791,191.09 7791,222 v1(7744,269)
  Bottom Copper w8: R151.2@6790,210 J15.2@6840,210 ; v1(7744,269) 7748.12,273.12 7777.88,273.12 7791.38,286.62 U33.12@7791.38,308.5
SDA_OUT_HDR: J15.4 R150.2 U33.9 | length 1790.5
  Layer 12 (SIG4) w3.3: J15.4@6940.65,210 J15.4@6940,210 6915,210 6870,255 6815,255 6760,200 6760,82.3 6798.6,43.7 7773.5,43.7 7800,70.2 7800,158.26 7804.95,163.21 7804.95,188.87 7800,193.82 7800,230.8 7824.6,255.4 7824.6,269.6 7836.65,281.65 7878.35,281.65 v1(7881,279)
  Bottom Copper w8: R150.2@6890,210 J15.4@6940,210 ; U33.9@7838.62,308.5 7838.62,303.38 7854,288 7872,288 v1(7881,279)
SDA_OUT_USB: R150.1 U17.33 | length 7432.4
  Top Copper w5: U17.33@931.91,755.29 932.19,755 v1(1059,755)
  Bottom Copper w5: v1(1059,755) 1059,229 1192,96 3874,96 3993,215 3993,316 4108,431 4541,431 4643,329 4643,202 4749,96 5508,96 5846,434 5894,434 6043,583 6437.86,583 6643,377.86 6643,205.46 6679.46,169 6871.05,169 R150.1@6890,187.95
SDA_USB: R151.1 U17.34 | length 7334.3
  Top Copper w5: U17.34@931.91,774.97 935.38,771.5 v1(1086.5,771.5)
  Bottom Copper w5: v1(1086.5,771.5) 1086.5,236.5 1215,108 3868,108 3979,219 3979,324 4099,444 4550,444 4657,337 4657,206 4755,108 5504,108 5841,445 5890,445 6038,593 6442,593 6653,382 6653,209.6 6675.43,187.17 R151.1@6790,187.17
SDI_ADC: U1.G8 U34.11 | length 1231.6
  Layer 8 (PWR/SIGNAL3) w3.3: v14@6348.25,1359.25 6364.1,1343.41 6598.59,1343.41 7023.01,918.99 v3@7023.01,588
  Bottom Copper w8: U34.11@7009.87,549.5 7009.87,575.87 v3(7022,588)
  other v14: 6347.24,1359.25
SDI_ADC_HDR: J15.22 R59.2 U30.3 | length 1219.4
  Layer 7 (PWR/SIGNAL2) w3.3: v3(7018,411) 7018,383 6985,350 6985,200 7026,159 7789,159 J15.22@7840,210
  Bottom Copper w8: U30.3@7012.87,361.5 7012.87,391.87 7018,397 v3(7018,411) ; R59.2@7790,210 J15.22@7840,210
SDI_ADC_USB: R59.1 U17.13 | length 8730.4
  Top Copper w4: U17.13@624.82,696.23 595.23,696.23 586,687 586,485 v1(665,406)
  Layer 3 (SIG1) w3.3: v1(665,406) 665,225 823,67 3917,67 3983,133 3983,322 4071,410 4393,410 4748,55 5334.94,55 5420,140.06 5420,235 5608.4,423.4 5912.6,423.4 6003.25,514.05 6472.53,514.05 6666.1,320.48 6666.1,195.96 6807.06,55 7745,55 7779.48,89.48 7779.48,177.43 v1(7781,178.95)
SDI_FMC: J1.G33 R74.2 U13.2 | length 1480.1
  Layer 12 (SIG4) w4: v3(7170.98,477.4) 7173.45,477.4 7190.98,494.93 7190.98,505.62 7227.31,541.95 7527,541.95 7585.5,600.45 7585.5,663.71 7697.74,775.95 8399.05,775.95 v1(8425,750)
  Bottom Copper w8: v3(7170.98,477.4) 7172.87,475.5 U13.2@7172.87,429.84
SDI_LMKX: U6.20 U32.5 U52.17 | length 5949.4
  Top Copper w5: v1(5643.21,1292.79) 5646.21,1295.79 5646.21,1306.79 5652.56,1313.15 U52.17@5652.56,1319.2
  Layer 3 (SIG1) w3.3: v1@7249.91,2201.1 7249.4,2200.6 7230,2220 7079,2220 6988,2129 6920,2129 6865,2074 6865,818 7160.75,522.25 7254.75,522.25 7343,434 7364.04,434 7373.88,443.84 ; 7373.88,443.88 7376,446 7419,446 7434.01,430.99 v3@7434.01,378
  Layer 8 (PWR/SIGNAL3) w3.3: v1(5643.21,1292.79) 5643.21,1254.21 5612,1223 5445,1223 5339,1329 5339,1529 5430,1620 5430,2114.95 5785.05,2470 6880,2470 7000,2350 7000,2268 7048,2220 7230,2220 v1(7248.9,2201.1)
  Bottom Copper w8: U32.5@7407.24,348.62 7415.17,348.62 7433,366.46 v3(7433,378)
  Bottom Copper w11.5: v1(7248.9,2201.1) U6.20@7248.9,2225
SDI_LMKX_HDR: J15.14 R85.2 U32.3 | length 359.4
  Layer 8 (PWR/SIGNAL3) w3.3: v3(7385,423) 7385,305 7440,250 J15.14@7440,210
  Bottom Copper w8: U32.3@7367.87,356.5 7367.87,376.87 7385,394 v3(7385,423) ; R85.2@7390,210 J15.14@7440,210
SDI_LMKX_USB: R85.1 U17.23 | length 8008.5
  Top Copper w4: U17.23@807.89,650.96 807.89,564.11 819,553 v1(819,447)
  Layer 3 (SIG1) w3.3: v1(819,447) 819,210 938.52,90.48 3901.48,90.48 3957,146 3957,338 4058,439 4406,439 4768,77 5332.97,77 5402,146.03 5402,242 5600.35,440.35 5905.58,440.35 5996.23,531 6479.55,531 6683.05,327.5 6683.05,202.98 6735.03,151 7373,151 v1(7390,134)
  Bottom Copper w5: v1(7390,134) R85.1@7390,187.95
SDO_ADC: U1.H8 U34.9 | length 1182.6
  Layer 8 (PWR/SIGNAL3) w3.3: v14(6347.24,1327.76) 6362.89,1312.11 6578.89,1312.11 6982.3,908.7 6982.3,607.29 v3@6963.01,588
  Bottom Copper w8: v3(6962,588) 6978.38,571.62 U34.9@6978.38,549.5
SDO_ADC_FMC: J1.G34 R178.2 | length 1279.9
  Layer 12 (SIG4) w4: v3@7283.05,466 7584.05,466 7713,594.95 7713,617.95 7777,681.95 8406.95,681.95 v1(8425,700)
  Layer 12 (SIG4) w6: v3(7282,464.95) v3@7283.05,466
  Bottom Copper w6: R178.2@7258.02,460 7277.05,460 v3(7282,464.95)
SDO_ADC_HDR: J15.18 R76.2 U30.12 | length 866.4
  Layer 12 (SIG4) w3.3: v1(6960,261.51) 6988.49,290 7170,290 7225,345 7397.13,345 7467.13,275 7538.95,275 7603.95,210 J15.18@7640,210
  Bottom Copper w8: v1(6960,261.51) 6981.38,282.89 U30.12@6981.38,298.5 ; R76.2@7590,210 J15.18@7640,210
SDO_ADC_USB: R76.1 U17.15 | length 8258.7
  Top Copper w4: U17.15@650.41,650.96 650.41,511.59 v1(660,502)
  Layer 3 (SIG1) w3.3: v1(660,502) 694,468 840,468 861,447 861,240 1001,100 3890,100 3944,154 3944,339 4053,448 4418,448 4779.3,86.7 5330.44,86.7 5393.3,149.56 5393.3,246.82 5595.48,449 5902,449 5993,540 6482.79,540 6691.7,331.09 6691.7,206.56 6737.26,161 7563.05,161 v1(7590,187.95)
SDO_LMKX: R34.2 R70.1 U33.2 | length 6733.5
  Top Copper w5: R70.1@5768.2,1298.79 5809.21,1298.79 v1(5818.21,1307.79)
  Layer 3 (SIG1) w3.25: v1@7188.33,2600.06 cw(c7189.9,2600.06) v1(7188.79,2601.17)
  Layer 3 (SIG1) w3.3: v1@7188.33,2600.06 7261.8,2600.06 7317.86,2544 7317.86,2334.14 7427,2225 7427,2090 7392,2055 7095.75,2055 6991.9,1951.15 6991.9,1308.1 7555.01,744.99 7555.01,572 7700.01,427 7798.55,427 v3@7799.55,428
  Layer 8 (PWR/SIGNAL3) w3.3: v1(5818.21,1307.79) 5818.21,1274.21 5638,1094 5511,1094 5302,1303 5302,1749 5413,1860 5413,2132.95 5461,2180.95 5654.85,2373.8 5762.05,2481 6875,2481 6966,2572 7159.62,2572 v1(7188.79,2601.17)
  Bottom Copper w8: v3(7799.55,428.53) 7807.13,420.95 U33.2@7807.13,371.5
SDO_LMKX_FMC: J1.G36 U14.3 | length 1085.9
  Layer 12 (SIG4) w4: v1(7554,359.95) 7603.05,409 7606.63,409 7616,418.37 7616,443.63 7733.33,560.95 7795,560.95 7907,672.95 8336,672.95 8349,659.95 8349,633.95 8360,622.95 8385,622.95 8407.95,600 v1(8425,600)
  Bottom Copper w4: v1(7554,359.95) v1@7554.25,359.7
  Bottom Copper w8: U14.3@7554.25,335 v1@7554.25,359.7
SDO_LMKX_HDR: J15.8 R148.2 U33.16 | length 945.9
  Layer 12 (SIG4) w3.3: J15.8@7140,210 7140,198.3 7172,166.3 7666.3,166.3 7690,190 7690,260 v1(7670,280)
  Bottom Copper w8: R148.2@7090,210 J15.8@7140,210 ; v1(7670,280) 7670,380 7680,390 7730,390 7756.38,363.62 U33.16@7767.76,363.62
SDO_LMKX_USB: R148.1 U17.26 | length 7644.2
  Top Copper w5: U17.26@866.94,650.96 866.94,619.06 v1(903,583)
  Bottom Copper w5: v1(903,583) 903,304 1136,71 3887,71 4020,204 4020,303 4120,403 4528,403 4614,317 4614,192 4735,71 5514.14,71 5855.14,412 5901.57,412 6016,526.43 6466.14,526.43 6617.79,374.79 6617.79,202.39 6755.17,65 7071,65 7090,84 R148.1@7090,187.95
SYNCB_ADC: U1.C2 U59.4 | length 2406.9
  Layer 8 (PWR/SIGNAL3) w3.3: v1@4236.32,701.32 4591.69,701.32 4606.01,687 4709,687 4729,707 4820,707 5054,941 5767,941 6098,1272 6129,1272 6143,1286 6143,1307 6149.11,1313.11 6164.34,1313.11 6173.92,1322.69 6173.92,1469.59 v14(6158.27,1485.24) v14@6159.28,1485.24
  Bottom Copper w11.5: U59.4@4234.69,718.19 4234.69,701.32 4235,701 v1(4235.31,701.32)
SYNCB_I: J25.1 R255.1 U59.2 | length 489.6
  Bottom Copper w11.5: J25.1@4000,600 3995,605 R255.1@3995,673.98 4025,673.98 4050,698.98 4050,795 4084,829 4191,829 4215,805 U59.2@4215,741.81
SYNCB_O: J1.H32 J24.1 R254.2 | length 4661.9
  Layer 7 (PWR/SIGNAL2) w4: J24.1@4130,600 4201.95,671.95 5087.04,671.95 5137.04,621.95 5296.73,621.95 5505.5,413.18 6164.66,413.18 6165.63,414.14 6208.37,414.14 6209.34,413.18 6721.77,413.18 7107.54,798.95 8017,798.95 8042,823.95 8351.05,823.95 v1(8375,800)
  Layer 5 (PWR1) w4: J24.1@4130,600 J24.1@4155.05,600
  Bottom Copper w11.5: J24.1@4130,600 R254.2@4130,673.98
SYSREF_ADC_LMK_N: C61.2 R49.2 R360.2 | length 3316.1
  Bottom Copper w10.5: v1(5849.48,1118.95) 5849.48,1129.54 ccw(c5820.54,1129.54) 5841,1150 ccw(c5833.76,1142.76) 5833.76,1153 5763,1153 ccw(c5763,1126.06) 5743.95,1145.11 5724.92,1126.08 cw(c5693.34,1157.66) 5693.34,1113 5491.31,1113 cw(c5491.31,1171.31) 5450.08,1130.08 5363.37,1216.79 cw(c5456,1309.42) 5325,1309.42 5325,1993 cw(c5385.36,1993) 5342.68,2035.68 5749.63,2442.63 cw(c5842.26,2350) 5842.26,2481 6481.58,2481 cw(c6481.58,2350) 6574.21,2442.63 6856.93,2159.91 ccw(c6905,2207.98) 6905,2140 6916.44,2140 cw(c6916.44,2134.96) R360.2@6920,2138.52 6920,2138.09 R49.2@6946.81,2138.09
SYSREF_ADC_LMK_P: C60.2 R39.2 R359.2 | length 3315.8
  Bottom Copper w10.5: v1(5848.48,1221.15) 5848.48,1199.98 cw(c5840.02,1199.98) 5846,1194 cw(c5821.86,1218.14) 5821.86,1184 5763,1184 ccw(c5763,1126.06) 5722.03,1167.03 5703,1148 cw(c5693.34,1157.66) 5693.34,1144 5491.31,1144 cw(c5491.31,1171.31) 5472.01,1151.99 5385.29,1238.71 cw(c5456,1309.42) 5356,1309.42 5356,1993 cw(c5385.36,1993) 5364.59,2013.75 5560.42,2209.58 5568.62,2217.78 cw(c5576.51,2209.9) 5584.39,2217.78 ccw(c5594.04,2227.43) 5603.7,2217.78 5616.56,2230.65 ccw(c5606.91,2240.3) 5616.56,2249.96 cw(c5624.45,2257.84) 5616.56,2265.72 5617.42,2266.58 5771.55,2420.71 cw(c5842.26,2350) 5842.26,2450 5977,2450 5986.1,2450 cw(c5986.1,2436.35) 5999.75,2436.35 5999.75,2433.65 ccw(c6013.4,2433.65) 6013.4,2420 6031.6,2420 ccw(c6031.6,2433.65) 6045.25,2433.65 6045.25,2438.25 cw(c6057,2438.25) 6057,2450 6117,2450 6128.9,2450 cw(c6128.9,2439.15) 6139.75,2439.15 ccw(c6153.4,2439.15) 6153.4,2425.5 6171.6,2425.5 ccw(c6171.6,2439.15) 6185.25,2439.15 cw(c6196.1,2439.15) 6196.1,2450 6207,2450 6481.58,2450 cw(c6481.58,2350) 6552.29,2420.71 6835.01,2137.99 ccw(c6905,2207.98) 6905,2109 6916.21,2109 ccw(c6916.21,2114.36) R359.2@6920,2110.57 6920,2113.09 R39.2@6946.81,2113.09
SYSREF_ADC_LMX_N: C306.2 R258.1 U52.18 | length 340
  Top Copper w10: R258.1@5672.21,1272.79 U52.18@5672.24,1319.2
  Top Copper w10.5: R258.1@5667.41,1266.88 5643.91,1243.38 5643.91,1172.09 5665.72,1155.05 C306.2@5827.08,1155.05
SYSREF_ADC_LMX_P: C52.2 R259.1 U52.19 | length 339.5
  Top Copper w10: U52.19@5691.93,1319.2 R259.1@5692.21,1269.79
  Top Copper w10.5: R259.1@5696.71,1266.88 5720.21,1243.38 5720.21,1191.79 5728.21,1183.79 5743.21,1183.79 5750.21,1190.79 5750.21,1232.79 5758.21,1240.79 5774.21,1240.79 5783.21,1231.79 5783.21,1189.79 5788.21,1184.79 5825.8,1184.79 C52.2@5826.05,1185.05
SYSREF_ADC_N: C61.1 C306.1 U1.L1 | length 307.5
  Top Copper w10.5: C61.1@5851.04,1154.26 cw(c5851.04,1156.97) C61.1@5849.08,1155.07 5850.17,1154 5960,1154 ccw(c5960,1248.15) 6026.58,1181.58 6066.86,1221.86 cw(c6095,1193.72) 6095,1233.52 6113.4,1233.52 6113.65,1233.27 U1.L1@6126.77,1233.27
SYSREF_ADC_P: C52.1 C60.1 U1.K1 | length 306
  Top Copper w10.5: C60.1@5848.08,1185.03 5960,1185 ccw(c5960,1248.15) 6004.66,1203.5 6044.94,1243.78 cw(c6095,1193.72) 6095,1264.52 6113.4,1264.52 6113.65,1264.76 U1.K1@6126.77,1264.76
SYSREF_SMA: J2.1 R32.1 | length 2108.6
  Layer 3 (SIG1) w3.3: v12(4710,2415) 4744,2449 4813.38,2449 4830.32,2465.94 4872.52,2465.94 4889.46,2449 6706,2449 v1(6745,2410)
  Layer 3 (SIG1) w11.5: v12(4710,2415) v12@4715,2415
  Bottom Copper w11.5: v1(6745,2410) R32.1@6762.2,2392.79
TDI_FMC: J1.D30 R105.2
  other v2: 8575,900
TDIODE_N: J16.1 R21.1 U1.K3 | length 1405.1
  Layer 12 (SIG4) w3.3: v1(6017,1080) 6040,1080 6063,1103 6063,1166 6145.92,1248.92 6173.92,1248.92 v22(6189.76,1264.76)
  Bottom Copper w6: R21.1@5185,602.99 J16.1@5185,700 5225.8,700 5232.8,707 5232.8,738.14 5290.66,796 5470.8,796 5663.84,989.04 5950.38,989.04 6017,1055.66 v1(6017,1080)
TDIODE_P: J16.2 R20.1 U1.K2 | length 1349.7
  Layer 12 (SIG4) w3.3: v1(6039,1110) 6039,1158 6145.76,1264.76 v22(6158.27,1264.76)
  Bottom Copper w6: J16.2@5285,700 5251.8,700 5244.8,707 5244.8,733.17 5295.63,784 5475.77,784 5668.81,977.04 5960.04,977.04 6038,1055 6038,1109 v1(6039,1110) ; R20.1@5295,602.99 J16.2@5295,690
TDO_FMC: J1.D31 R105.1
  other v2: 8575,850
USB_D_N: J20.2 R156.1 | length 114.7
  Top Copper w5: R156.1@424.7,820.3 R156.1@425,820
  Top Copper w11.5: J20.2@310.47,820.3 R156.1@424.7,820.3
USB_P_P: J20.3 R157.1 | length 114.6
  Top Copper w5: R157.1@424.78,788.8 R157.1@424.98,789
  Top Copper w11.5: J20.3@310.47,788.8 R157.1@424.78,788.8
VA11: C139.1 C140.1 C141.1 C167.2 C168.2 C169.2 C170.2 C171.2 C172.2 C173.2 C174.2 C175.2 C176.2 FB9.2 TP5.1 U1.C5 U1.D2 U1.D3 U1.D5 U1.E5 U1.F5 U1.G5 U1.H5 U1.J2 U1.J3 U1.J5 U1.K5
  other v1: 3610,1525 3692.09,1526.5 3762.09,1526.5 3832.09,1526.5 3691,1574 3761,1574 3831,1574 3611,1575 3607.91,1634.57 3690,1638.94 3760,1638.94 3830,1638.94
  other v16: 6252.76,1264.76 6158.27,1296.26 6189.76,1296.26 6252.76,1296.26 6252.76,1327.76 6252.76,1359.25 6252.76,1390.75 6252.76,1422.24 6158.27,1453.74 6189.76,1453.74 6252.76,1453.74
  other v21: 6252.76,1485.24
VA19: C178.2 C179.2 C180.2 C181.2 C182.2 C183.2 C201.1 C202.1 C203.1 FB10.2 TP9.1 U1.C4 U1.D4 U1.E2 U1.E3 U1.E4 U1.F4 U1.G4 U1.H2 U1.H3 U1.H4 U1.J4 U1.K4
  other v1: 3605,1110 3687.09,1111.5 3757.09,1111.5 3827.09,1111.5 3688.63,1156.5 3758.63,1156.5 3828.63,1156.5 3603,1158 3688.54,1208.5 3758.54,1208.5 3828.54,1208.5 3602.91,1210
  other v17: 6221.26,1264.76 6221.26,1296.26 6158.27,1327.76 6189.76,1327.76 6221.26,1327.76 6221.26,1359.25 6221.26,1390.75
  other v18: 6158.27,1422.24 6189.76,1422.24 6221.26,1422.24 6221.26,1453.74 6221.26,1485.24
VBG_ADC: TP1.1 U1.C3 | length 3721.2
  Layer 12 (SIG4) w3.3: TP1.1@3193,149 3280,236 3321,236 3935,850 5298,850 5363,915 5892,915 5994,1017 5994,1129 6145.41,1280.41 6164.75,1280.41 6174,1289.66 6174,1469.47 v23(6189.76,1485.24)
VD11: C124.2 C125.2 C145.1 C146.1 C147.1 C156.2 C157.2 C158.2 C159.2 C160.2 C161.2 C162.2 C163.2 FB2.2 FB8.2 TP7.1 U1.C9 U1.C10 U1.E9 U1.E10 U1.G7 U1.H7 U1.H9 U1.H10 U1.K9 U1.K10 | length 3436.5
  Layer 7 (PWR/SIGNAL2) w4: v1(3360,498.5) 3628.55,498.5 4140,1009.95 6055,1009.95 6103,1057.95 6103,1268.95 6114.31,1280.26 6133.4,1280.26 6133.9,1280.76 6196.39,1280.76 6196.9,1280.26 6290.88,1280.26 6300.75,1290.13 6300.75,1311.26 6315.75,1326.26 v11(6315.75,1327.76)
  other v1: 3216.91,312 3249,320 3307.09,321.5 3377.09,321.5 3218,358 3250,377 3217,394 3216.91,430 3249,430 3285,457 3358,459 3220,498.5 3290,498.5
  other v11: 6378.74,1264.76 6410.24,1264.76 6378.74,1327.76 6410.24,1327.76 6315.75,1359.25 6378.74,1422.24 6410.24,1422.24 6378.74,1485.24 6410.24,1485.24
VDD18-USB: C80.1 C81.2 C82.2 U17.2 U17.31 U17.43 | length 141.6
  Top Copper w8: v1(602,912.5) 602.27,912.77 U17.2@624.82,912.77 ; U17.43@906.32,958.04 v1(923.46,958.04) ; U17.31@931.91,715.92 v1(954.92,715.92)
  Bottom Copper w8: v1@601,913.5 v1(602,912.5) C82.2@624.98,912.5 ; v1(923.46,958.04) 923.46,986.95 C80.1@925,988.5 ; C81.2@931.91,715.92 v1(954.92,715.92)
VDDD33: C76.2 C77.2 C78.2 C79.2 C89.2 C229.1 C230.1 C231.1 C415.1 C416.1 C417.1 C422.1 C424.1 C426.1 C428.1 C429.1 C430.1 C431.1 C432.1 C433.1 FB6.2 J19.1 L14.1 L15.1 R24.2 R25.2 R26.2 R29.1 R165.1 R167.2 R168.2 R169.2 R177.2 R217.1 R805.2 R851.2 TP11.1 U4.2 U13.13 U14.13 U15.13 U17.16 U17.36 U17.44 U17.50 U18.8 U30.14 U32.14 U33.14 U34.5 U34.14 U34.15 U34.16 U36.8 U41.5 U42.5 | length 1148.4
  Top Copper w8: v1(447,569) R165.1@447,587.95 ; v1(670.09,627.59) U17.16@670.09,650.96 ; U17.50@768.52,958.04 v1(768.52,981.98) ; U17.44@886.63,958.04 v1(886.63,984.13) v1@888,985.5 ; U17.36@931.91,814.34 v1(955.34,814.34) ; v1(937.18,1138.18) U18.8@980.41,1138.18
  Top Copper w12: v3(8521,70) R217.1@8538.98,70
  Bottom Copper w8: L15.1@503.88,910.5 v1(503.88,935.38) ; v1(512.38,686.88) L14.1@512.38,711.5 ; v1(670.09,627.59) C77.2@670.09,650.96 ; v1(755,1160) R167.2@755.02,1138.18 756.02,1137.18 R168.2@756.02,1113 ; C79.2@768.52,958.04 v1(768.52,981.98) ; R169.2@780.02,1064 781.02,1063 v1(804,1063) ; C78.2@886.63,958.04 v1(886.63,984.13) ; C89.2@918.05,1138 937,1138 v1(937.18,1138.18) ; C76.2@931.91,814.34 v1(955.34,814.34) ; C433.1@6915,311.02 6926.1,322.13 U30.14@6957.76,322.13 ; C428.1@6915,493.98 6932.02,493.98 v3(6936,490) ; v3@6941,490 v3(6936,490) ; U34.5@6954.76,494.38 6940.38,494.38 v3(6936,490) ; U34.16@7049.24,494.38 U34.15@7049.24,510.13 7058.2,510.13 v3@7065.07,517 ; U34.14@7049.24,525.87 7056.07,525.87 7056.13,525.94 v3@7065.07,517 ; v3(7067,517) v3@7065.07,517 ; C422.1@7100,373.98 7113.98,373.98 v3(7115,375) ; C430.1@7272.21,292.79 7272.21,301.21 v3(7282,311) 7288.13,317.13 U32.14@7312.76,317.13 ; v3(7628,390) 7640,402 C424.1@7640,408.98 ; C429.1@7722.21,317.79 7722.21,329.79 v3(7722,330) 7734,329.98 7736.15,332.13 U33.14@7767.76,332.13 ; v3(7781.02,453.5) 7793.9,466.38 U15.13@7817.76,466.38
  Bottom Copper w9: C417.1@5146.02,540 5146.02,523.74 v1(5147.88,521.88) U4.2@5147.88,498.28
  Bottom Copper w10: U42.5@8182.29,173.82 v1@8207.82,173.82 ; R851.2@8301.98,152.4 R805.2@8301.98,201.42
  Bottom Copper w11.5: v1(4710.79,219.21) 4710,220 4717.99,227.99 U36.8@4717.99,262.28 ; v1(4752.99,153.03) R177.2@4752.99,169.57 R177.2@4752.99,170.04 ; U41.5@8182.29,71.14 v1(8206.86,71.14) 8208,70 C432.1@8228.98,70 ; v1@8207.82,173.82 v1(8209,175) C431.1@8228.98,175
  Bottom Copper w12: C415.1@5136.97,583.19 5146.02,574.13 C417.1@5146.02,540
  Bottom Copper w15: C415.1@5136.97,583.19 5137.99,584.21 C416.1@5137.99,620
  Bottom Copper w15.5: v1(5110,265) R24.2@5110,282.01 ; v1(5195,250) R25.2@5195,267.01 ; v1(5245,260) R26.2@5245,277.01
  other v1: 5467.01,205 6921.27,317.12 3608.24,2344.89 3690.32,2346.39 3760.32,2346.39 3830.32,2346.39 3612,2419 3694.09,2420.5 3764.09,2420.5 3834.09,2420.5 3610,2455 3692.09,2456.5 3762.09,2456.5 3832.09,2456.5
  other v3: 8302,183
